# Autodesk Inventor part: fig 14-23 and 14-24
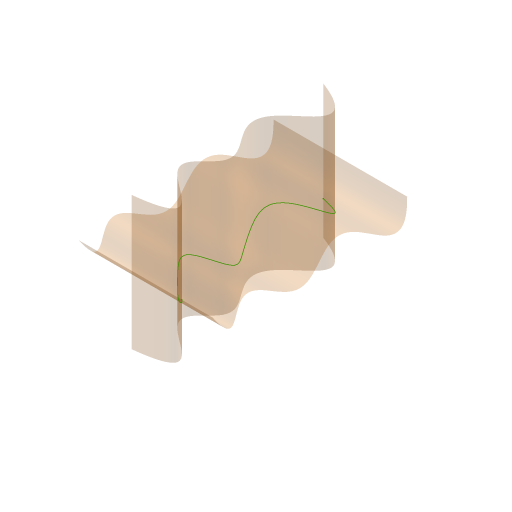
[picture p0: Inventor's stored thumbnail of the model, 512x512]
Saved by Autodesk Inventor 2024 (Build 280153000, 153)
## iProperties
Created: 2007-05
Part Number: fig 14-23 and 14-24
Document SubType Name: Modeling
Designer: Administrator
Density: 1 g/cm^3
Material: Generic
Appearance: Default
Author: Administrator
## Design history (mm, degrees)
sketch "Sketch3"
  geometry: 7 further points
  constraints: 7 other
extrude_surface "ExtrusionSrf1" sketch "Sketch3" dims "d0" = 50, "d1" = 0
sketch "Sketch4"
  geometry: 7 further points
  constraints: 7 other
extrude_surface "ExtrusionSrf2" sketch "Sketch4" dims "d2" = 50, "d3" = 0
sketch "3D Sketch1"
  node "3D Intersection1"
node "Sketch1"
node "Sketch2"
body "Srf1"
body "Srf2"
